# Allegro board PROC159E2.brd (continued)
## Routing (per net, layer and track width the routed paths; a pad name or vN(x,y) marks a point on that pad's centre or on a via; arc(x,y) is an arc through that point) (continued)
N34830437: length 5.6
  BOTTOM w0.147: C91.2 88.04,53.55 88.09,53.6 U13.8 ; C91.2 87.59,53.4 U13.9 ; C91.2 88.04,52.86 87.75,52.57 87.75,52.09 R70.1
N34869480: length 3.3
  TOP w0.147: R432.2 R431.2 82.51,35.37 82.19,35.05 U78.6
N34869775: length 1.3
  BOTTOM w0.147: C57.1 R29.2
N35052540: length 1.2
  BOTTOM w0.147: U17.5 103.31,13.13 R7.1
N35052638: length 1.7
  TOP w0.147: U4.10 95.02,15.27 94.85,15.1 R18.1
N35052879: length 2.3
  TOP w0.147: C9.1 99.43,18.92 99.8,18.55 U3.6
N35052899: length 2.1
  BOTTOM w0.147: R6.2 103.63,11.6 103.31,11.93 102.97,11.93 102.55,12.35 U17.6
N35052954: length 1.8
  BOTTOM w0.147: R2.2 103.54,15.18 103,14.63 103,14.22 102.7,13.93 U17.3
N35052969: length 2.8
  BOTTOM w0.147: U17.9 101.05,12.39 100.71,12.05 99.9,12.05 TP1.1
N35053013: length 1.9
  BOTTOM w0.147: R8.1 100,13.53 U17.11
N35053423: length 1.7
  TOP w0.147: C16.1 95.8,15.1 95.52,15.38 U4.11
N35053536: length 10.2
  BOTTOM w0.147: v1(78.3,21.45) 76.12,19.27 76.12,15.35 76.84,14.63 C24.1 R22.2
N35053695: length 2
  BOTTOM w0.147: U5.7 86.18,16.26 86.5,16.58 R23.1
N35053732: length 1.3
  BOTTOM w0.147: R24.1 C23.2
N35056553: length 1.7
  TOP w0.147: LD1.2 102.2,14.86 101.86,14.53 R1.2
N35059517: length 4.7
  TOP w0.147: U1.B10 v1(60.98,46.43)
  BOTTOM w0.147: R141.2 62.69,48.77 60.98,47.06 v1(60.98,46.43)
N35065419: length 12.4
  TOP w0.147: v1(103.42,36.08) 103.19,36.31 U7.12
  L08_SIG2 w0.091: v1(94.4,37.06) 94.77,37.06 95.22,36.61 100.67,36.61 101.82,35.46 102.79,35.46 v1(103.42,36.08)
  BOTTOM w0.147: R42.1 v1(94.4,37.06)
N35071225: length 10.1
  TOP w0.147: v1(106.62,35.3) 106.29,35.62 106.29,35.63 106.19,35.73 106.19,36.36 106.19,36.36 U7.18
  L03_SIG1 w0.091: v1(106.62,35.3) 107.21,34.7 107.21,29.91 v1(108.02,29.1)
  BOTTOM w0.147: v1(108.02,29.1) 107.57,28.65 R435.1
N35137924: length 4
  TOP w0.147: TP64.1 69.49,95.24 70.12,94.6 71.37,94.6 71.81,95.04 J8.38
N35139843: length 12.4
  TOP w0.147: U7.34 v1(104.69,46.09)
  L03_SIG1 w0.091: v1(111.04,53.24) 108.34,50.54 108.34,48.55 106.39,46.6 105.21,46.6 v1(104.69,46.09)
  BOTTOM w0.147: R142.1 110.92,53.12 v1(111.04,53.24)
N35230144: length 2.2
  TOP w0.147: U18.5 30.35,56.38 29.93,56.79 R439.1
N35230147: length 1.6
  TOP w0.147: U18.2 40.11,53.84 R440.1
N35230153: length 1.6
  TOP w0.147: U18.7 R442.1
N35244293: length 3.7
  TOP w0.147: R452.1 36.1,43.66 35.64,44.11 33.3,44.11 U19.D2
N35244332: length 3.2
  TOP w0.147: U19.C4 30.26,42.08 28.81,42.08 28.58,42.3 R453.1
N35244360: length 3.3
  TOP w0.147: R454.1 28.03,44.8 28.59,44.24 30.26,44.24 U19.D4
N35244387: length 2
  TOP w0.147: R455.1 28.48,43.57 28.71,43.8 29.25,43.8 29.39,43.66 U19.D5
N35244414: length 3.2
  TOP w0.147: R456.1 31.33,46.63 31.85,46.11 U19.E3
N35244441: length 3.4
  TOP w0.147: U19.E2 33.85,45.66 R457.1
N35244468: length 2.6
  TOP w0.147: U19.E1 34.38,44.66 35.13,45.41 R458.1
N35248046: length 4.3
  TOP w0.147: U19.D3 32.43,44.24 32.43,44.83 32.6,45.01 R451.1
N35252647: length 1.6
  TOP w0.147: U18.3 40.11,55.11 R441.1
N35271296: length 2
  TOP w0.147: TP78.1 17.96,25.36 18.42,24.91 U29.8
N35329968: length 5.4
  TOP w0.147: U1.L3 v1(54.58,38.43)
  BOTTOM w0.147: R117.2 51.52,39.69 52.77,38.43 v1(54.58,38.43)
N35329989: length 5.3
  TOP w0.147: U1.M3 v1(54.58,37.63)
  BOTTOM w0.147: R118.2 52.07,38.54 52.52,38.1 54.11,38.1 v1(54.58,37.63)
N35342843: length 1.5
  TOP w0.147: U57.15 44.2,105.26 R371.1
N35343433: length 1.6
  TOP w0.147: U57.14 44.07,103.99 R372.1
N35343436: length 1.5
  TOP w0.147: R373.1 44.2,102.72 U57.13
N35343439: length 1.6
  TOP w0.147: U57.12 44.07,101.45 R374.1
N35343442: length 1.5
  TOP w0.147: U57.11 44.2,100.18 R375.1
N35343445: length 1.5
  TOP w0.147: U57.10 44.2,98.91 R376.1
N35345342: length 1.8
  BOTTOM w0.147: R378.1 18.51,73.05 18.51,73.06 U58.7
N35373997: length 4.6
  TOP w0.147: v1(43.94,78.73) U46.5 41.91,78.73 41.28,79.36 R315.1
  BOTTOM w0.147: v1(43.94,78.73) 44.18,78.48 R314.1
N35375175: length 2.1
  BOTTOM w0.147: R34.1 J20.1
N35376496: length 3.2
  BOTTOM w0.147: R31.1 R175.2 17.69,17.25 17.71,17.22 J21.1
N35387120: length 3.5
  TOP w0.147: U29.7 22.59,24.91 22.9,25.22 22.9,26.45 23.28,26.83 R116.1
N35387809: length 4.6
  TOP w0.147: v1(44.79,41.82) 43.93,40.95 R1678.1
  BOTTOM w0.147: v1(44.79,41.82) 43.79,40.82 U80.8
N35395797: length 2.2
  TOP w0.147: U20.15 52.77,64.96 53.35,64.38 R461.1
N35537520: length 11.8
  TOP w0.147: v1(90.8,35.17) 91.18,34.79 94.86,34.79 95.27,34.38 R20.1 95.28,32.65 95.69,32.24 95.69,32.22 95.72,32.19 Q13.4
  BOTTOM w0.147: R469.1 89.85,34.21 v1(90.8,35.17)
N35538921: length 2.2
  BOTTOM w0.147: Q12.3 88.42,33.07 88.87,32.62 R469.2
N35654609: length 1.7
  TOP w0.147: Q20.2 R3832.2
N35654631: length 1.7
  TOP w0.147: LD19.2 Q20.3
N35656175: length 1.3
  TOP w0.147: LD2.2 R47.2
N35656498: length 1.3
  TOP w0.381: R3833.2 LD20.2
N35656998: length 1.1
  TOP w0.147: R3834.2 LD21.2
N35657235: length 1.3
  TOP w0.381: R3835.2 LD22.2
N35672996: length 3.3
  TOP w0.147: SW15.2 62.89,55.21 62.51,55.59 R3842.2
N35712813: length 56.6
  TOP w0.147: J22.2 72.06,23.08 67.23,23.08 65.88,21.73 50.86,21.73 47.58,25.01 40.89,25.01 40.05,25.84 39.14,25.84 37.94,27.04 37.94,28.66 36.88,29.73 27.1,29.73 24.79,27.42 R116.2
N35805242: length 14.2
  TOP w0.147: v1(76.94,48.25) 76.94,46.83 75.55,45.44 70.26,45.44 67.99,43.17 67.32,43.17 U1.F18
  BOTTOM w0.147: R247.1 77.2,48.5 v1(76.94,48.25)
N35805430: length 8.2
  TOP w0.147: U1.C18 67.69,45.23 69.37,46.91 71.11,46.91 v1(72.71,48.51)
  BOTTOM w0.147: v1(72.71,48.51) 73.07,48.51 73.21,48.66 R255.1
N35805533: length 16.9
  TOP w0.147: v1(75.59,46.26) 76.34,47.01 76.34,48.81 76.82,49.29 R248.1 ; U1.G16 v1(65.78,42.43)
  BOTTOM w0.114: v1(65.78,42.43) 65.78,42.43 66.18,42.03 67.63,42.03 67.8,42.2
  BOTTOM w0.147: 67.8,42.2 68.66,43.06 68.66,44.82 69.92,46.08 74.96,46.08 75.14,46.26 v1(75.59,46.26)
N35805539: length 12.7
  TOP w0.147: U1.E17 66.58,44.03 67.97,44.03 69.97,46.03 73.99,46.03 74.75,46.79 74.75,47.85 75.64,48.73 R249.1
N35805550: length 12.3
  TOP w0.147: U1.E18 68.04,43.63 70.14,45.73 74.17,45.73 75.56,47.12 v1(75.56,47.99)
  BOTTOM w0.147: R250.1 75.73,48.61 75.56,48.44 v1(75.56,47.99)
N35805561: length 13.7
  TOP w0.147: R251.1 74.42,48.31 73.93,47.82 v1(73.93,46.78) ; U1.F16 v1(65.78,43.23)
  BOTTOM w0.114: v1(65.78,43.23) 65.78,43.23 66.18,42.83 66.88,42.83 67.07,43.02
  BOTTOM w0.147: v1(73.93,46.78) 73.34,46.78 73.05,46.49 69.73,46.49 67.95,44.71 67.95,43.9 67.07,43.02
N35805574: length 10.2
  TOP w0.147: U1.F15 v1(64.98,43.23)
  BOTTOM w0.114: 66.36,43.84 66.15,43.63 65.38,43.63 v1(64.98,43.23)
  BOTTOM w0.147: R252.1 70.85,47.2 70.49,46.84 69.36,46.84 66.36,43.84
N35805586: length 9.5
  TOP w0.147: R253.1 71.98,48.31 71.03,47.37 v1(70.27,47.37) ; U1.E16 v1(65.78,44.03)
  BOTTOM w0.147: v1(65.78,44.03) 69.12,47.37 v1(70.27,47.37)
N35805597: length 9.8
  TOP w0.147: U1.D18 67.82,44.43 69.71,46.32 71.74,46.32 v1(73.93,48.51)
  BOTTOM w0.147: R254.1 74.43,48.66 74.29,48.51 v1(73.93,48.51)
N35805610: length 9.6
  TOP w0.147: R256.1 73.2,48.31 71.5,46.62 69.59,46.62 67.79,44.82 66.57,44.82 U1.D17
N35805636: length 5.7
  TOP w0.147: v1(70.27,48.51) 69.81,48.51 69.57,48.27 69.57,48.14 67.46,46.03 U1.B18
  BOTTOM w0.147: R257.1 69.63,48.68 69.8,48.51 v1(70.27,48.51)
N35805639: length 5.1
  TOP w0.147: R258.1 69.54,48.68 67.28,46.42 66.57,46.42 U1.B17
N35805644: length 6.1
  TOP w0.147: U1.D16 v1(65.78,44.83)
  BOTTOM w0.147: R259.1 68.41,47.46 v1(65.78,44.83)
N35805649: length 6.9
  TOP w0.147: U1.C17 66.57,45.62 67.53,45.62 69.8,47.89 70.41,47.89 70.76,48.24 R260.1
N35805656: length 3.8
  TOP w0.147: U1.A17 66.52,47.17 66.52,48.24 67.57,49.29 R261.1
N35805662: length 4.8
  TOP w0.147: U1.C16 v1(65.78,45.63)
  BOTTOM w0.147: v1(65.78,45.63) 66.35,46.2 66.35,47.12 67.19,47.96 R262.1
N35805667: length 5.5
  TOP w0.147: U1.C15 v1(64.98,45.63) ; v1(66.22,48.87) 66.43,49.08 R1652.1
  BOTTOM w0.114: 65.38,47.56 65.38,46.03 v1(64.98,45.63)
  BOTTOM w0.147: v1(66.22,48.87) 65.38,48.03 65.38,47.56
N35805672: length 6.1
  TOP w0.147: U1.D15 v1(64.98,44.83) ; R1653.1 v1(65.2,48.85)
  BOTTOM w0.114: 64.58,47.56 64.58,45.23 v1(64.98,44.83)
  BOTTOM w0.147: 64.58,47.56 64.58,48.24 v1(65.2,48.85)
N35820709: length 1.6
  TOP w0.147: SW14.2 R3858.2
N35821153: length 4.8
  BOTTOM w0.147: U88.19 83.59,107.33 83.93,107.67 86.37,107.67 86.59,107.46 R1399.2
N35824901: length 1.9
  BOTTOM w0.147: U81.9 70.82,29.38 70.37,29.83 R475.2
N35842882: length 1.6
  BOTTOM w0.147: R3870.2 U90.9
N35844058: length 1.6
  TOP w0.147: SW16.2 R3872.2

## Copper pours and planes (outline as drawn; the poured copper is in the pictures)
DGND on TOP (solid shape): 92.69,98 90.51,98 90.51,105.68 92.69,105.68
DGND on TOP (solid shape): 71.89,87.53 72.1,87.53 72.1,86.46 69.99,86.46 69.27,87.18 69.27,87.62 71.4,87.62 71.53,87.74 71.89,87.74
DGND on TOP (solid shape): 47.7,66.96 47.47,66.96 47.47,67.16 46.43,67.16 46.43,66.96 46.23,66.96 45.59,66.33 45.59,65.99 44.83,65.99 44.83,66.92 45.78,67.87 47.7,67.87
DGND on TOP (solid shape): 43.08,60.62 43.19,60.65 43.25,60.55 43.25,60.16 44.49,58.92 44.49,58.47 44.43,58.38 44.32,58.4 42.77,59.95 42.77,60.31
DGND on TOP (solid shape): 42.2,62.25 42.23,62.3 42.29,62.29 42.67,61.9 42.67,61 42.38,60.7 42.26,60.68 42.2,60.77 42.2,60.87 41.22,60.87 41.22,62.01 41.02,62.01 41.02,62.24 42.2,62.24
DGND on TOP (solid shape): 48.14,33.61 48.33,33.61 48.33,33.41 49.46,33.41 49.46,32.43 51.4,32.43 51.4,32.67 51.65,32.67 51.87,32.89 51.98,32.91 52.04,32.82 52.04,32.36 51.58,31.9 51.3,31.9 51.3,32.08 49.55,32.08 49.55,31.1 49.37,31.1 49.37,31.3 48.33,31.3 48.33,31.1 47.84,31.1 47.84,32.58 46.64,32.58 46.64,34.13 47.62,34.13
DGND on TOP (solid shape): 58.23,77.22 58.25,77.11 58.16,77.05 58.01,77.05 56.59,75.62 56.47,75.6 56.41,75.7 56.41,77.72 55.73,78.4 55.71,78.51 55.8,78.57 56.88,78.57
DGND on TOP (solid shape): 87.32,19.34 87.44,19.36 87.5,19.27 87.5,15.93 88.26,15.17 88.29,15.06 88.19,14.99 83.58,14.99 83.49,15.04 83.48,15.13 83.5,15.21 83.49,15.3 83.52,15.38 83.59,15.41 86.48,15.41 86.48,18.5
DGND on TOP (solid shape): 105.1,89.79 105.07,89.7 105.06,89.61 105.06,88.66 104.49,88.66 104.32,88.63 104.17,88.54 104.15,88.53 104.12,88.53 104.12,88.5 104.11,88.49 103.99,88.26 104,88.01 103.99,87.92 103.91,87.88 102.93,87.88 102.83,87.94 102.85,88.05 104.75,89.94 105.1,89.94
DGND on TOP (solid shape): 43.19,27.3 43.26,27.4 43.37,27.37 43.49,27.27 43.64,27.23 43.66,27.23 44.99,25.89 45.01,25.78 44.92,25.72 41.23,25.72 40.42,26.53 39.44,26.53 39.37,26.6 39.35,26.71 39.44,26.77 40.16,26.77 40.16,27.32 40.75,27.32 40.75,27.29 41.79,27.29 41.79,27.32 42.15,27.32 42.15,27.29 43.19,27.29
DGND on TOP (solid shape): 51.75,36.56 51.84,36.53 52.22,36.15 52.96,36.15 53,36.1 53.02,36.03 53,35.96 52.96,35.91 52.54,35.91 51.67,35.04 51.56,35.01 51.5,35.11 51.5,35.15 50.64,35.15 50.64,35.59 51.05,35.59 51.12,35.6 51.19,35.62 51.43,35.62 51.43,35.88 51.44,35.94 51.45,35.98 51.45,36.24 51.6,36.39 51.64,36.45 51.68,36.5
DGND on TOP (solid shape): 81.82,88.89 81.92,88.87 82.81,87.97 84.71,87.97 85.49,87.19 85.49,85.96 85.43,85.87 85.32,85.89 85.01,86.19 82.35,86.19 81.68,86.86 81.68,86.88 81.62,87.05 81.49,87.18 81.44,87.25 81.47,87.34 81.52,87.39 81.52,88.45 81.46,88.51 81.5,88.55 81.51,88.56 81.66,88.67 81.75,88.83
DGND on TOP (solid shape): 69.37,94.92 69.44,94.89 69.56,94.78 69.59,94.69 69.54,94.62 69.42,94.48 69.38,94.3 69.38,94.13 69.34,94.13 69.34,93.29 70,93.29 70,92.15 70.96,92.15 70.96,92.22 71.22,92.22 71.32,92.31 71.61,92.31 71.73,92.19 71.89,92.19 71.89,91.72 71.67,91.72 71.52,91.57 71.5,91.57 71.38,91.54 71.27,91.47 70.91,91.83 69.36,91.83 69,92.2 69,94.5 68.99,94.52 68.96,94.61 69.02,94.69 69.17,94.76 69.29,94.88
DGND on TOP (solid shape): 85.07,85.35 85.07,84.75 85.91,83.91 85.91,82.62 85.85,82.53 85.74,82.55 85.16,83.12 84.16,83.12 83.56,82.53 83.29,82.53 83.2,82.55 83.11,82.56 82.53,82.56 82.38,82.53 82.24,82.46 82.13,82.44 82.07,82.54 82.07,83.31 82.14,83.4 82.25,83.38 82.52,83.28 82.79,83.39 83.25,83.85 83.25,83.95 83.34,83.95 83.34,84.99 82.38,84.99 82.38,84.09 82.24,83.95 82.2,83.91 82.17,83.86 82.07,83.88 82.07,85.64 84.78,85.64
DGND on TOP (solid shape): 98.94,90.34 99,90.44 99.11,90.42 99.14,90.39 99.14,88.98 98.62,88.46 98.62,87.22 97.19,85.79 97.08,85.77 97.02,85.86 97.02,86.93 97.08,87.02 97.19,87 98.22,87.1 98.05,88.13 98.05,88.28 98.46,88.69 98.57,88.96 98.45,89.3 98.48,89.37 98.94,89.83
DGND on TOP (solid shape): 37.67,28.55 37.67,27.39 36.78,27.39 36.7,27.43 36.69,27.53 36.46,28.03 35.97,27.78 35.9,27.71 35.8,27.73 35.45,28.08 34.37,28.08 34.37,28.69 32.95,28.69 32.95,27.98 27.73,27.98 27.63,28.04 27.65,28.15 28.43,28.92 29.96,28.92 30.43,28.88 30.58,29.32 30.6,29.41 30.68,29.45 36.76,29.45
DGND on TOP (solid shape): 82.66,92.94 82.72,93.03 82.83,93.01 82.85,92.99 84.79,92.99 84.79,90.57 85.1,90.27 85.25,90.17 85.42,90.13 85.67,90.13 85.84,90.17 85.99,90.27 86.22,90.5 86.29,90.48 86.34,90.47 86.38,90.46 86.38,90.23 86.34,90.23 86.04,90.01 86.05,89.65 86.06,89.54 85.97,89.49 85.02,89.49 85.02,88.53 84.96,88.51 84.94,88.52 83.04,88.52 81.71,89.86 81.71,89.88 81.59,90.12 81.35,90.23 81.31,90.24 81.3,90.28 81.3,92.45 81.62,92.45 81.62,92.36 82.66,92.36
DGND on TOP (solid shape): 82.34,69.56 82.4,69.47 82.4,69.32 82.49,69.32 82.49,68.89 82.93,68.45 82.93,67.38 82.89,67.3 82.8,67.28 82.31,66.92 82.8,66.55 82.89,66.53 82.93,66.45 82.93,65.07 82.9,65.01 82.89,64.97 82.82,64.9 82.72,64.93 81.76,65.88 81.76,69.31 81.8,69.39 81.88,69.41 82.07,69.43 82.23,69.53
DGND on TOP (solid shape): 98.87,85.47 98.92,85.45 98.91,85.39 98.84,85.21 98.86,85.02 98.85,84.92 98.77,84.87 98.69,84.87 98.69,82.93 98.82,82.93 98.82,82.59 96.37,80.14 95.53,80.14 95.24,80.02 95.14,79.71 95.14,79.69 95.09,79.64 95.04,79.69 95.04,81.13 97.56,83.65 97.67,83.67 97.73,83.57 97.73,82.93 96.11,81.31 96.09,81.3 95.94,80.67 96.57,80.83 96.57,80.84 98.39,82.65 98.39,85.1 98.76,85.47
DGND on TOP (solid shape): 30.79,8.02 30.9,8.04 30.96,7.95 30.96,6.36 30.92,6.28 30.84,6.26 30.4,5.88 30.84,5.5 30.92,5.48 30.96,5.4 30.96,4.59 31.11,4.44 31.14,4.41 31.14,4.4 31.46,4.09 31.47,4.03 31.42,4 31.36,4 31.36,2.35 30.72,2.35 30.72,4 30.69,4 30.69,4.26 30.24,4.72 30.24,6.21 30.28,6.21 30.62,6.59 30.28,6.97 30.24,6.97 30.24,7.47
DGND on TOP (solid shape): 73.96,89.53 74.2,89.41 74.46,89.44 74.56,89.43 74.6,89.35 74.6,88.73 74.81,88.73 74.86,88.68 74.88,88.64 74.86,88.6 74.81,88.56 74.6,88.56 74.6,87.93 74.81,87.93 74.96,87.82 75.14,87.79 75.26,87.79 75.26,87.58 74.8,87.58 74.8,87.49 75,87.49 75,87.13 74.8,87.13 74.8,86.86 72.77,86.86 72.77,87.13 72.57,87.13 72.57,87.49 72.77,87.49 72.77,87.53 72.96,87.53 72.96,87.57 73.11,87.57 73.28,87.74 73.3,87.75 73.65,88.15 73.25,88.51 73.18,88.53 73.15,88.61 73.15,89.14 72.96,89.14 72.96,89.79 73.22,89.79 73.28,89.84 73.65,89.84
DGND on TOP (solid shape): outline of 128 points within 62.52,61.98 70.88,67
DGND on TOP (solid shape): 88.9,12.75 88.93,12.8 88.99,12.79 89.05,12.73 89.05,12.09 89.83,11.3 92.18,11.3 94.8,8.68 95.34,8.68 95.44,8.61 95.42,8.5 94.57,7.66 94.57,4.04 94.75,3.86 94.75,2.65 94.12,2.65 94.12,4 94.09,4 94.09,7.68 93.46,8.31 93.43,8.42 93.52,8.48 93.73,9.17 93.14,8.77 93.12,8.68 93.04,8.64 93,8.64 92.92,8.68 92.9,8.77 92.87,9.06 92.66,9.28 92.6,9.36 92.65,9.45 92.49,10.16 92.2,9.5 92.23,9.39 92.13,9.32 89.81,9.32 89.08,8.59 88.97,8.57 88.9,8.66
DGND on TOP (solid shape): 77.69,103.59 77.8,103.61 77.86,103.52 77.86,100.67 77.81,100.58 77.71,100.58 77.14,100.25 77.71,99.92 77.81,99.92 77.86,99.83 77.86,96.49 77.87,96.49 77.9,96.4 77.84,96.32 77.74,96.25 77.66,96.14 77.63,96.12 77.6,96.11 77.53,96.13 77.45,96.14 77.35,96.14 77.34,96.18 77.28,96.36 77.15,96.5 77.11,96.59 77.15,96.67 77.32,97.18 76.89,97.5 76.05,97.5 75.84,97.29 75.74,97.27 75.67,97.36 75.47,97.36 75.47,98.61 72.1,98.61 72.1,97.65 69.08,97.65 69.08,95.91 69.04,95.83 68.96,95.81 68.77,95.82 68.59,95.77 68.49,95.77 68.44,95.86 68.44,98.37 68.95,98.88 75.61,98.88 76.85,100.12 76.95,100.62 76.43,100.96 76.45,101.07 76.83,101.44 76.83,102.73
DGND on TOP (solid shape): outline of 198 points within 46.15,60.55 52.61,66.79
DGND on TOP (solid shape): outline of 247 points within 64,2.55 67.44,12.89
DGND on TOP (solid shape): outline of 273 points within 83.99,64.39 88.44,80.81
DGND on TOP (solid shape): outline of 116 points within 71.49,90.33 75.52,98.03
DGND on TOP (solid shape): outline of 321 points within 58.65,91.03 67.26,99.36
DGND on TOP (solid shape): outline of 323 points within 80.74,42.73 93.98,56.92
DGND on TOP (solid shape): outline of 149 points within 27.18,57.03 44.2,68.43
DGND on TOP (solid shape): outline of 139 points within 81.3,95.64 88.4,105.86
DGND on TOP (solid shape): outline of 545 points within 98.63,2.65 108.73,9.48
DGND on TOP (solid shape): outline of 549 points within 62.13,14.63 82.76,22.8
DGND on TOP (solid shape): outline of 730 points within 67.34,34.33 83.76,51
DGND on TOP (solid shape): outline of 959 points within 43.1,22.6 68.58,31.35
DGND on TOP (solid shape): outline of 1416 points within 35.77,28.23 50.66,50.34
DGND on TOP (solid shape): outline of 1476 points within 53,26.7 82.83,36.96
DGND on TOP (solid shape): outline of 1628 points within 41.27,85.44 75.61,108.19
DGND on TOP (solid shape): outline of 2125 points within 31.51,2.35 63.43,21.45
DGND on TOP (solid shape): outline of 2328 points within 44.35,43.18 69.78,66.79
DGND on TOP (solid shape): outline of 2452 points within 86.77,55.25 113.74,108.19
DGND on TOP (solid shape): outline of 2377 points within 22.19,32.65 44.34,62.34
DGND on TOP (solid shape): outline of 2783 points within 46.03,63.51 75.56,94.26
DGND on TOP (solid shape): outline of 2885 points within 72.58,2.65 113.74,59.55
DGND on TOP (solid shape): outline of 5063 points within 10.02,2.35 50.67,78.39
DGND on L03_SIG1 (solid shape): 77.5,56.44 75.63,54.57 75.52,54.55 75.46,54.64 75.46,59.37 75.59,59.51 77.5,59.51
DGND on L03_SIG1 (solid shape): 93.22,103.64 93.22,103.6 93.16,103.5 93.05,103.53 92.7,103.87 90.49,103.87 90.39,103.97 90.39,104.32 92.55,104.32
DGND on L03_SIG1 (solid shape): 93.28,86.42 93.28,84.03 93.33,83.98 93.28,83.93 93.26,83.93 93.17,83.95 93.13,84.03 93.13,85.62 92.64,86.11 90.77,86.11 90.51,86.37 90.51,86.96 92.73,86.96
DGND on L03_SIG1 (solid shape): 70.5,99.43 71.75,98.19 71.75,97.12 71.69,97.03 71.58,97.05 70.73,97.9 70.73,99 70.34,99.39 70.4,99.44
DGND on L03_SIG1 (solid shape): 34.89,55.39 34.91,55.27 34.82,55.21 33.98,55.21 30.65,58.54 30.63,58.65 30.72,58.71 31.56,58.71
DGND on L03_SIG1 (solid shape): 72.83,39.93 72.92,39.87 72.9,39.76 72.54,39.41 69.94,39.41 69.85,39.47 69.87,39.58 70.22,39.93
DGND on L03_SIG1 (solid shape): 77.52,62.87 77.62,62.8 77.6,62.69 77.26,62.36 75.3,62.36 74.95,62 74.89,61.99 74.86,62.04 74.86,62.17 75.55,62.87
DGND on L03_SIG1 (solid shape): 88.02,70.38 88.13,70.4 88.19,70.31 88.19,66.95 87.88,66.64 87.77,66.62 87.71,66.71 87.71,70.07
DGND on L03_SIG1 (solid shape): 89.19,70.66 89.3,70.69 89.37,70.59 89.37,67.03 89.14,66.81 89.03,66.79 88.97,66.88 88.97,70.44
DGND on L03_SIG1 (solid shape): 91.39,56.24 91.46,56.33 91.57,56.31 92.29,55.59 92.29,53.62 92.22,53.52 92.11,53.55 91.39,54.27
DGND on L03_SIG1 (solid shape): 93.05,82.95 93.16,82.97 93.22,82.88 93.22,78.14 92.83,77.75 92.72,77.73 92.66,77.82 92.66,82.56
DGND on L03_SIG1 (solid shape): 95.58,70.9 95.64,70.99 95.75,70.97 96.18,70.54 96.18,66.27 96.12,66.18 96.01,66.2 95.58,66.63
DGND on L03_SIG1 (solid shape): 59.75,31.7 59.86,31.72 59.92,31.63 59.92,31.43 59.57,31.07 59.57,29.34 58.68,28.45 58.1,28.45 57.83,28.17 57.77,28.22 57.78,28.28 57.78,28.34 58.62,29.18 58.62,30.57
DGND on L03_SIG1 (solid shape): 77.49,61.89 77.55,61.9 77.58,61.85 77.58,60.3 77.29,60.01 75.39,60.01 75.36,59.98 75.25,59.96 75.18,60.05 75.18,61.53 75.51,61.86 77.47,61.86
DGND on L03_SIG1 (solid shape): 87.06,48.83 87.13,48.92 87.24,48.9 87.6,48.54 87.6,47.15 86.92,46.48 86.81,46.46 86.75,46.55 86.75,46.94 87.06,47.25
DGND on L03_SIG1 (solid shape): 87.61,80.14 87.72,80.16 87.78,80.06 87.78,77.5 88.84,76.44 88.84,76.07 88.78,75.98 88.67,76 87.58,77.09 87.58,80.11
DGND on L03_SIG1 (solid shape): 89.41,45.14 89.5,45.08 89.48,44.96 89.42,44.91 89.42,41.46 88.3,40.33 88.19,40.31 88.12,40.4 88.12,44.24 89.02,45.14
DGND on L03_SIG1 (solid shape): 104.47,44.39 104.57,44.32 104.54,44.21 103.64,43.31 103.64,38.91 101.48,36.74 101.42,36.73 101.39,36.78 101.39,36.82 103.18,38.61 103.18,43.16 104.41,44.39
DGND on L03_SIG1 (solid shape): 70.24,45.31 70.35,45.33 70.41,45.23 70.41,45.2 70.77,44.84 70.39,44.46 69.66,44.46 67.81,42.61 67.73,42.58 67.65,42.62 67.63,42.65 67.63,42.7
DGND on L03_SIG1 (solid shape): 71.91,68.34 72.02,68.36 72.08,68.27 72.08,68.24 72.54,67.78 71.7,66.94 71.46,67.18 71.42,67.18 71.32,67.24 71.34,67.35 71.4,67.41 71.4,67.83
DGND on L03_SIG1 (solid shape): 89.38,48.84 89.44,48.93 89.55,48.91 89.78,48.68 89.78,46.24 89.45,45.91 88.7,45.91 87.75,44.96 87.64,44.94 87.57,45.03 87.57,45.55 89.38,47.36
DGND on L03_SIG1 (solid shape): 94.62,60.88 94.73,60.9 94.79,60.81 94.79,60.33 95.51,59.6 95.51,50.72 94.9,50.11 94.79,50.08 94.72,50.18 94.72,57.06 93.81,57.98 93.81,60.07
DGND on L03_SIG1 (solid shape): 55.72,29.71 55.84,29.74 55.9,29.64 55.9,29.47 55.9,20.85 55.84,20.76 55.73,20.78 55.54,20.96 55.54,29.53
DGND on L03_SIG1 (solid shape): 79.71,29.3 79.77,29.39 79.88,29.37 81.17,28.08 81.17,26.83 81.11,26.74 81,26.76 80.88,26.87 80.54,26.87 80.54,27.45 80.07,27.92 80.07,28.71 79.71,29.08
DGND on L03_SIG1 (solid shape): 88.76,57.32 88.82,57.42 88.93,57.39 88.97,57.36 88.97,53.15 89.42,52.7 89.42,51.4 90.6,50.21 90.6,49.58 90.54,49.49 90.43,49.51 88.71,51.23 88.71,56.84 88.51,57.03 88.76,57.28
DGND on L03_SIG1 (solid shape): 19.08,14.59 19.19,14.61 19.25,14.52 19.25,10.18 19.48,9.95 19.48,7.95 19.41,7.86 19.3,7.88 19.18,7.96 19.03,7.99 19.01,7.99 18.62,8.38 18.62,14.13
DGND on L03_SIG1 (solid shape): 93.39,45.44 92.72,44.78 92.72,41.79 91.74,40.81 91.63,40.79 91.57,40.88 91.57,43.94 93.21,45.58 93.21,47.82 92.78,48.24 92.78,48.45 92.91,48.45 93.01,48.47 93.09,48.53 93.22,48.66 93.26,48.71 93.29,48.77 93.3,48.81 93.39,48.81
DGND on L03_SIG1 (solid shape): 108.21,45.71 108.31,45.65 108.29,45.53 106.74,43.99 106.74,38.93 106.3,38.49 104.41,38.49 103.51,37.59 103.27,37.59 103.18,37.65 103.2,37.76 104.14,38.7 104.14,43.1 105.04,44.01 106.46,44.01 108.16,45.71
DGND on L03_SIG1 (solid shape): 60.84,39.6 60.9,39.69 61.02,39.67 61.25,39.44 62.66,39.44 62.72,39.38 62.72,37.32 63.08,36.96 63.07,36.93 63.05,36.87 63.05,36.8 63.03,36.72 62.95,36.69 62.46,36.69 62.42,36.73 62.42,37.16 62.09,37.49 60.91,37.49 60.84,37.56
DGND on L03_SIG1 (solid shape): 68.38,64.77 68.49,64.8 68.55,64.7 68.55,64.62 69.04,64.13 69.59,64.13 69.66,64.2 69.71,64.21 69.74,64.16 69.74,56.27 69.71,56.22 69.66,56.23 69.61,56.28 68.14,56.28 67.7,56.72 67.7,64.1
DGND on L03_SIG1 (solid shape): 90.72,59.32 90.83,59.34 90.9,59.25 90.9,54.06 91.52,53.44 91.54,53.36 91.49,53.28 91.4,53.2 91.34,53.09 91.26,53.03 91.17,53.06 90.43,53.79 90.43,59.03
DGND on L03_SIG1 (solid shape): 83.81,68.72 83.9,68.75 83.97,68.69 84.01,68.63 84.05,68.57 84.09,68.5 84.06,68.43 83.85,68.22 83.85,67.72 82.29,67.72 81.91,67.34 81.1,67.34 80.25,68.19 80.25,68.22 80.28,68.27 80.33,68.25 80.5,68.08 83.17,68.08
DGND on L03_SIG1 (solid shape): 23.93,15.87 24.04,15.85 24.07,15.81 24.07,9.44 22.71,8.08 22.71,6.91 22.64,6.81 22.53,6.84 22.49,6.88 22.49,8.65 23.65,9.81 23.65,15.3 23.74,15.39 23.74,15.57 23.82,15.67 23.86,15.79
DGND on L03_SIG1 (solid shape): 90.97,87.98 92.43,87.98 92.78,87.63 92.8,87.52 92.71,87.46 90.59,87.46 89.51,88.54 89.5,88.54 89.41,88.58 89.41,88.68 89.44,88.8 89.43,88.93 89.45,89.02 89.53,89.06 89.9,89.06
DGND on L03_SIG1 (solid shape): 38.62,53.09 38.71,53.03 38.69,52.92 37.49,51.71 36.56,51.71 36.48,51.75 36.46,51.83 36.46,51.86 36.46,51.98 36.44,52.08 36.38,52.16 36.22,52.32 31.86,52.32 30.69,51.15 30.64,51.15 30.6,51.18 30.61,51.23 32.47,53.09
DGND on L03_SIG1 (solid shape): 46.32,36.53 46.32,35.82 46.49,35.65 46.33,35.5 45.53,35.5 45.46,35.53 45.43,35.62 45.35,35.93 45.05,36.06 45.03,36.06 44.78,36.3 44.76,36.39 44.82,36.47 44.89,36.51 44.96,36.57 46.28,36.57
DGND on L03_SIG1 (solid shape): 48.24,93.31 48.36,93.33 48.42,93.24 48.42,92.03 51.01,89.44 51.04,89.36 50.99,89.28 50.84,89.14 50.8,88.94 50.8,88.92 47.92,86.04 47.8,86.02 47.74,86.11 47.74,92.81
DGND on L03_SIG1 (solid shape): 90.14,85.79 90.21,85.88 90.32,85.86 90.57,85.61 92.43,85.61 92.63,85.42 92.63,84.01 92.59,83.92 92.49,83.91 92.36,83.94 92.23,83.92 92.14,83.93 92.1,84.02 92.1,84.16 91.48,84.77 90.92,84.77 90.14,85.55
DGND on L03_SIG1 (solid shape): 95.71,82.72 95.75,82.71 95.81,82.69 95.87,82.69 96.09,82.69 96.09,81.83 94.79,80.53 94.68,80.51 94.61,80.6 94.61,82.44 94.86,82.69 94.94,82.71 95.02,82.67 95.36,82.48 95.68,82.69
DGND on L03_SIG1 (solid shape): 85.65,93.9 85.73,93.85 85.83,93.83 86.07,93.83 86.16,93.76 86.14,93.65 84.88,92.39 84.88,85.16 84.82,85.07 84.71,85.09 84.56,85.23 82.86,85.23 82.71,85.39 82.71,92.77 83.77,93.83 84.62,93.83 84.81,94.01 84.92,93.9 85,93.85 85.1,93.83 85.25,93.83 85.34,93.85 85.42,93.9 85.54,94.01
DGND on L03_SIG1 (solid shape): 32.34,14.44 32.44,14.47 32.51,14.39 32.66,14.14 32.95,14.07 33.03,14.05 33.07,13.97 33.07,7.28 32.33,6.55 32.25,6.52 32.18,6.56 32.04,6.68 31.87,6.72 31.84,6.72 31.57,6.99 31.57,9.73 32.13,10.3 32.13,14.24
DGND on L03_SIG1 (solid shape): 56.32,44.09 56.32,42.86 56.29,42.79 56.21,42.76 56.17,42.76 56.13,42.76 56.05,42.78 56.02,42.86 56.02,42.95 55.71,43.25 55.71,43.27 55.61,43.47 55.41,43.56 55.4,43.56 55.35,43.61 55.44,43.71 55.46,43.71 55.65,43.84 55.71,44.06 55.74,44.14 55.81,44.17 56.24,44.17
DGND on L03_SIG1 (solid shape): 53.12,47.29 53.12,47.07 52.61,47.07 50.46,44.92 50.35,44.9 50.28,44.99 50.28,45.69 50.66,46.06 50.74,46.09 50.81,46.05 51.39,46 51.34,46.58 51.3,46.66 51.33,46.74 51.96,47.37 53.04,47.37
DGND on L03_SIG1 (solid shape): 82.78,44.8 82.85,44.9 82.96,44.86 83.81,44.42 84.65,44.86 84.77,44.9 84.84,44.8 84.84,43.5 83.28,41.94 83.28,36.4 83.24,36.36 83.19,36.37 83.15,36.4 83.07,36.46 82.98,36.48 82.78,36.48
DGND on L03_SIG1 (solid shape): 92.23,105.68 92.31,105.62 92.4,105.6 92.64,105.6 92.73,105.54 92.71,105.43 92.67,105.39 92.67,105.21 92.55,105.09 90.75,105.09 90.32,105.52 90.31,105.57 90.45,105.62 90.54,105.68 90.65,105.79 90.76,105.68 90.84,105.62 90.94,105.6 91.09,105.6 91.19,105.62 91.27,105.68 91.38,105.79 91.5,105.68 91.58,105.62 91.67,105.6 91.82,105.6 91.92,105.62 92,105.68 92.11,105.79
DGND on L03_SIG1 (solid shape): 80.84,44.03 80.84,43.28 80.8,43.2 80.72,43.18 80.26,42.92 80.5,42.45 80.57,42.38 80.54,42.29 79.48,41.22 79.42,41.28 79.43,41.36 79.43,41.51 79.42,41.6 79.36,41.69 79.25,41.79 79.17,41.85 79.08,41.87 78.85,41.87 78.85,42.31 80.65,44.11 80.65,44.13 80.71,44.16
DGND on L03_SIG1 (solid shape): 65.78,29.13 65.88,29.16 65.95,29.07 66.12,28.79 66.44,28.75 66.54,28.73 66.58,28.65 66.58,26.63 66.21,26.26 66.09,26.24 66.03,26.34 65.91,26.64 65.59,26.73 65.5,26.75 65.47,26.83 65.47,28.82
DGND on L03_SIG1 (solid shape): 80.74,40.73 80.85,40.76 80.91,40.66 80.91,40.65 80.93,40.55 80.98,40.47 81.19,40.26 81.92,40.26 81.92,39.65 81.56,39.29 81.48,39.26 81.41,39.3 81.38,39.33 81.18,39.54 81.1,39.54 81.1,39.6 81.1,39.62 80.76,40.17 80.43,39.62 80.43,39.6 80.43,39.54 80.26,39.54 80.26,40.25
DGND on L03_SIG1 (solid shape): 90.56,71.87 90.67,71.89 90.73,71.8 90.73,71.35 91.35,70.74 91.35,65.82 92.16,65 92.16,64.6 92.12,64.52 92.03,64.51 91.54,64.14 92.03,63.78 92.12,63.76 92.16,63.68 92.16,62.55 92.1,62.46 91.99,62.48 91.68,62.79 89.81,62.79 89.55,63.05 89.55,65.89 90.2,66.55 90.2,71.52
DGND on L03_SIG1 (solid shape): 45.78,41.4 45.82,41.42 45.85,41.4 45.93,41.35 46.02,41.34 46.29,41.34 46.31,41.31 46.33,41.28 46.41,41.2 46.49,41.15 46.59,41.13 46.65,41.13 46.65,41.07 46.67,40.97 46.72,40.89 46.8,40.81 46.88,40.76 46.98,40.74 47.04,40.74 47.04,40.64 47.02,40.55 46.94,40.52 46.72,40.52 46.56,40.36 46.49,40.33 46.33,40.44 46.25,40.49 46.15,40.51 46.1,40.51 46.1,40.57 46.08,40.67 46.02,40.75 45.94,40.83 45.86,40.88 45.77,40.9 45.71,40.9 45.71,40.99 45.69,41.09 45.64,41.17 45.59,41.21
DGND on L03_SIG1 (solid shape): 34.31,61.27 34.41,61.21 34.38,61.1 33.8,60.51 33.7,60.49 33.63,60.55 32.89,60.52 33.56,60.2 33.67,60.23 33.74,60.13 33.74,58.07 36.02,55.78 36.04,55.67 35.95,55.61 35.37,55.61 31.77,59.21 29.85,59.21 29.75,59.27 29.78,59.38 31.66,61.27
DGND on L03_SIG1 (solid shape): outline of 95 points within 44.33,57.72 48.6,64.96
DGND on L03_SIG1 (solid shape): 49.03,93.63 49.03,93.62 49.31,93.34 49.69,93.46 49.87,93.46 49.93,93.4 49.96,93.3 49.89,93.23 49.64,92.7 50.21,92.56 50.27,92.57 50.29,92.52 50.29,92.47 52.28,90.47 52.31,90.38 52.24,90.31 51.99,90.02 52.11,89.65 52.11,89.29 52.05,89.2 51.94,89.22 48.92,92.24 48.92,93.62 48.98,93.68
DGND on L03_SIG1 (solid shape): 101.39,27.82 101.45,27.92 101.56,27.9 102.81,26.64 102.81,22.16 102.75,22.06 102.64,22.09 102.08,22.09 102.12,21.53 102.16,21.45 101.98,21.07 102.16,20.69 102.12,20.61 101.98,20.34 102.07,20.06 102.1,19.99 102.07,19.92 102.03,19.87 101.96,19.82 101.87,19.85 101.83,19.89 101.83,27.04 101.39,27.48
DGND on L03_SIG1 (solid shape): 23.11,11.8 23.15,11.72 23.15,10.02 21.99,8.86 21.99,6.88 21.97,6.32 22.53,6.34 22.64,6.37 22.71,6.28 22.71,4.97 23.36,4.31 23.55,4.31 23.59,4.27 23.61,4.21 23.56,4.18 21.47,4.18 21.3,4.35 21.28,4.43 21.32,4.5 21.47,4.8 21.34,5.1 21.34,8.79 22.06,9.51 22.09,9.51 22.46,9.8 22.26,10.24 22.2,10.31 22.23,10.4 22.68,10.85 22.68,11.71 22.73,11.8 22.81,11.81 22.92,11.8 23.02,11.81
DGND on L03_SIG1 (solid shape): 48.88,33.9 48.99,33.93 49.05,33.83 49.05,33.5 46.01,30.46 46.01,29.41 44.93,28.33 44.83,28.3 44.76,28.38 44.11,28.6 44.33,27.95 44.41,27.88 44.38,27.78 44.21,27.61 44.11,27.58 44.04,27.66 43.4,27.88 43.61,27.23 43.69,27.16 43.67,27.06 43.41,26.8 42.35,26.8 37.5,21.95 37.39,21.93 37.33,22.02 37.33,22.35
DGND on L03_SIG1 (solid shape): outline of 120 points within 48.52,81.16 51.79,88.81
DGND on L03_SIG1 (solid shape): 95.56,7.41 95.64,7.44 95.72,7.4 95.93,7.24 96.2,7.26 96.21,7.27 96.27,7.27 96.27,7.18 96.06,6.97 96.04,6.97 95.66,6.58 96.07,6.21 96.17,6.15 96.15,6.04 96.06,5.96 96.04,5.96 95.66,5.5 96.18,5.22 96.19,5.23 96.25,5.23 96.25,5.13 96.06,4.94 96.04,4.94 95.72,4.77 95.69,4.4 95.69,4.32 95.63,4.26 95.57,4.24 95.52,4.2 95.33,4.01 95.28,4.06 95.15,4.2 95.07,4.25 94.97,4.27 94.68,4.27 94.4,3.99 94.4,3.54 94.12,3.54 94,3.66 94,4.44 95.53,5.98 95.53,7.38
DGND on L03_SIG1 (solid shape): 111.12,51.94 111.23,51.96 111.29,51.86 111.91,50.79 113.14,50.97 113.25,50.99 113.31,50.89 113.31,50.13 113.25,50.04 113.14,50.05 111.29,49.24 113.14,48.43 113.25,48.45 113.31,48.35 113.31,45.87 112.74,45.3 111.88,45.3 110.99,44.4 110.88,44.38 110.82,44.48 110.82,51.63
DGND on L03_SIG1 (solid shape): outline of 130 points within 39.05,58.1 45.72,63.03
DGND on L03_SIG1 (solid shape): 30.27,16.07 30.36,16.01 30.34,15.9 28.93,14.49 28.93,12.66 28.9,12.58 28.81,12.56 28.38,12.18 28.81,11.8 28.9,11.78 28.93,11.7 28.93,9.47 28.89,9.39 28.81,9.37 28.6,9.37 28.43,9.25 27.73,9.25 27.71,9.23 27.6,9.21 27.53,9.3 27.53,13.99 27.58,14.08 27.67,14.09 28.15,14.28 28.01,14.77 27.96,14.84 27.99,14.93 28.54,15.48 28.56,15.48 28.87,15.62 28.94,15.95 28.96,16.03 29.04,16.07
DGND on L03_SIG1 (solid shape): 40.97,47.9 40.97,47.22 40.93,47.14 40.84,47.12 40.35,46.81 40.74,46.38 40.84,46.32 40.82,46.2 40.76,46.14 40.73,46.14 40.35,45.8 40.66,45.38 40.74,45.31 40.71,45.21 40.21,44.71 40.1,44.69 40.04,44.79 40.04,45.62 38.83,46.84 38.35,46.84 38.35,48.55 38.2,48.71 38.12,48.76 38.03,48.78 37.91,48.78 37.82,48.76 37.74,48.71 37.58,48.55 37.46,48.68 37.38,48.73 37.28,48.75 37.15,48.75 37.06,48.73 36.98,48.68 36.84,48.54 36.79,48.53 36.76,48.58 36.76,48.63 36.57,48.82 36.55,48.93 36.64,48.99 38.26,48.99 38.42,49.15 38.47,49.23 38.49,49.32 38.52,49.51 38.59,49.54 39.33,49.54
DGND on L03_SIG1 (solid shape): 86.84,105.7 86.84,105.07 87.89,104.01 88.59,104.01 88.66,103.98 88.69,103.9 88.68,103.8 88.71,103.7 88.69,103.61 88.61,103.56 88,103.56 86.76,104.81 86.76,104.83 86.11,105.11 86.39,104.46 86.41,104.46 86.47,104.39 86.49,104.28 86.4,104.22 86,103.84 86.39,103.46 86.41,103.46 86.47,103.39 86.49,103.28 86.4,103.22 86.06,103.04 86.04,102.66 86.04,102.56 85.95,102.51 82.72,102.51 82.34,102.9 82.34,105.51 82.42,105.59 86.09,105.59 86.44,105.46 86.73,105.7 86.74,105.71 86.78,105.75
DGND on L03_SIG1 (solid shape): 83.36,32.3 83.42,32.39 83.53,32.37 84.25,31.65 84.25,22.6 88.49,18.36 88.49,16.79 89.92,15.37 89.94,15.26 89.84,15.19 89.6,15.19 86.04,18.76 83.99,18.76 83.58,19.16 83.58,28.11 82.78,28.92 82.78,29.12 83.08,29.12 83.29,29.33 83.34,29.41 83.36,29.5 83.36,29.8 83.15,30 83.1,30.05 83.29,30.24 83.31,30.26 83.33,30.29 83.38,30.34 83.46,30.33 83.98,30.77 83.31,30.92 83.24,30.88 83.16,30.91 83.1,30.97 83.29,31.16 83.31,31.18 83.33,31.21 83.38,31.25 83.46,31.25 83.98,31.68 83.31,31.83 83.24,31.79 83.16,31.82 83.1,31.88 83.29,32.07 83.34,32.15 83.36,32.25
DGND on L03_SIG1 (solid shape): outline of 179 points within 60.75,3.98 70.05,15.52
DGND on L03_SIG1 (solid shape): 34.44,58.76 36.33,56.88 45.97,56.88 46.05,56.84 46.07,56.75 46.44,56.27 46.81,56.75 46.83,56.84 46.91,56.88 48.29,56.88 49.2,55.97 49.22,55.86 49.13,55.79 45.54,55.79 45.46,55.84 45.45,55.93 45.09,56.43 44.73,55.93 44.71,55.84 44.63,55.79 44.28,55.79 44.2,55.83 44.18,55.92 43.81,56.37 43.44,55.92 43.42,55.83 43.34,55.79 42.71,55.79 42.63,55.84 42.62,55.94 42.29,56.5 41.95,55.94 41.95,55.84 41.86,55.79 36.71,55.79 34.23,58.27 34.23,58.67 34.27,58.74 34.35,58.77
DGND on L03_SIG1 (solid shape): outline of 214 points within 32.37,41.79 37.99,44.24
DGND on L03_SIG1 (solid shape): outline of 233 points within 104.55,16.37 113.74,29.23
DGND on L03_SIG1 (solid shape): outline of 236 points within 104.63,46.85 111.08,54.52
DGND on L03_SIG1 (solid shape): outline of 253 points within 51.58,57.15 58.72,72.54
DGND on L03_SIG1 (solid shape): outline of 277 points within 88.76,87.32 93.94,95.06
DGND on L03_SIG1 (solid shape): 84.14,56.02 84.2,56.12 84.31,56.09 85.82,54.59 85.85,54.5 85.8,54.43 85.61,53.96 86.05,53.72 86.13,53.69 86.17,53.62 86.17,53.56 86.11,53.56 86.1,53.56 85.59,53.23 86.05,52.83 86.13,52.8 86.17,52.73 86.17,52.67 86.11,52.67 86.1,52.67 85.59,52.34 86.05,51.94 86.13,51.92 86.17,51.84 86.17,49.54 86.56,49.14 86.56,47.46 86.25,47.14 86.25,44.52 85.51,43.78 85.4,43.76 85.34,43.85 85.34,49.03 84.9,49.46 84.9,50.95 84.94,51.02 85.02,51.05 85.47,51.42 85.02,51.8 84.94,51.82 84.9,51.9 84.9,51.95 84.96,51.95 84.97,51.95 85.47,52.28 85.02,52.69 84.94,52.71 84.9,52.79 84.9,52.84 84.96,52.84 84.97,52.84 85.47,53.17 85.02,53.58 84.94,53.6 84.9,53.68 84.9,53.73 84.96,53.73 84.97,53.73 85.4,54.3 84.71,54.12 84.64,54.03 84.53,54.05 84.14,54.44
DGND on L03_SIG1 (solid shape): outline of 129 points within 70.05,40.43 79.16,47.35
DGND on L03_SIG1 (solid shape): outline of 302 points within 22.32,55.05 31.43,61.98
DGND on L03_SIG1 (solid shape): outline of 288 points within 48.78,64.81 50.79,81.64
DGND on L03_SIG1 (solid shape): outline of 352 points within 68.69,82.49 71.75,94.72
DGND on L03_SIG1 (solid shape): outline of 349 points within 41.9,8.73 60.47,27.42
DGND on L03_SIG1 (solid shape): outline of 398 points within 62.22,13.81 70.28,25.17
DGND on L03_SIG1 (solid shape): outline of 457 points within 106.47,29.46 113.74,45.46
DGND on L03_SIG1 (solid shape): outline of 151 points within 30.1,34.12 48.43,45.49
DGND on L03_SIG1 (solid shape): outline of 500 points within 64.91,25.6 74.66,39.45
DGND on L03_SIG1 (solid shape): outline of 550 points within 49.44,64.55 57.21,89.9
DGND on L03_SIG1 (solid shape): outline of 541 points within 54.42,34.27 57.92,42.11
DGND on L03_SIG1 (solid shape): outline of 604 points within 46.93,12.68 55.24,26.2
DGND on L03_SIG1 (solid shape): outline of 767 points within 61.53,84.92 77.8,103.8
DGND on L03_SIG1 (solid shape): outline of 791 points within 98.94,2.65 113.74,16.1
DGND on L03_SIG1 (solid shape): outline of 798 points within 64.84,42.72 74.68,57.82
DGND on L03_SIG1 (solid shape): outline of 919 points within 54.16,51.97 72.52,74.02
DGND on L03_SIG1 (solid shape): outline of 966 points within 42.56,44.5 53.81,55.11
DGND on L03_SIG1 (solid shape): outline of 1243 points within 41.27,74.63 75.57,108.19
DGND on L03_SIG1 (solid shape): outline of 1475 points within 49.5,74.65 70.61,95.71
DGND on L03_SIG1 (solid shape): outline of 1840 points within 60.81,74.15 85.11,107.38
DGND on L03_SIG1 (solid shape): outline of 3037 points within 19.75,7.82 47.75,58.31
DGND on L03_SIG1 (solid shape): outline of 5359 points within 10.02,2.35 88.55,76.7
DGND on L03_SIG1 (solid shape): outline of 5654 points within 90.43,26.55 113.74,108.19
DGND on L08_SIG2 (solid shape): 103.34,26.96 102.56,26.18 102.45,26.16 102.39,26.26 102.39,29.07 102.9,29.59 103.34,29.59
DGND on L08_SIG2 (solid shape): 70.33,56.37 70.33,56.23 69.53,56.23 69.1,56.65 67.71,56.65 67.44,56.92 67.42,57.03 67.51,57.09 69.61,57.09
DGND on L08_SIG2 (solid shape): 106.52,45.2 106.58,45.3 106.69,45.27 107.76,44.21 107.76,38.71 107.49,38.44 107.25,38.68 107.25,44.32 106.52,45.05
DGND on L08_SIG2 (solid shape): 35.13,17.94 35.17,17.89 33.82,16.54 31.38,16.54 31.28,16.6 31.3,16.71 31.65,17.06 34.15,17.06 35.07,17.97
DGND on L08_SIG2 (solid shape): 85.06,105.24 84.73,104.91 82.4,104.91 81.85,104.35 81.75,104.33 81.68,104.41 81.66,104.46 81.65,104.5 81.63,104.53 82.84,105.74 85.06,105.74
DGND on L08_SIG2 (solid shape): 62.33,32.61 62.33,31.98 60.72,30.37 60.18,30.37 60.09,30.43 60.11,30.54 62.26,32.69
DGND on L08_SIG2 (solid shape): 23.88,15.72 23.88,14.6 24.46,14.03 24.46,13.18 24.4,13.09 24.29,13.11 23.72,13.68 23.72,15.37 23.74,15.39 23.74,15.57 23.81,15.65 23.85,15.75
DGND on L08_SIG2 (solid shape): 30.17,8.72 30.21,8.69 30.2,8.64 28.92,7.36 28.24,7.36 27.81,7.79 27.79,7.9 27.88,7.96 29.32,7.96 30.08,8.72
DGND on L08_SIG2 (solid shape): 35.24,15.73 35.35,15.75 35.41,15.66 35.41,14.68 34.79,14.06 33.81,14.06 32.14,12.38 32.01,12.38 31.96,12.41 31.97,12.47
DGND on L08_SIG2 (solid shape): 46.49,30.92 46.58,30.86 46.56,30.75 45.86,30.05 43.13,30.05 43.03,30.11 43.06,30.22 43.76,30.92
DGND on L08_SIG2 (solid shape): 47.87,19.07 47.97,19 47.95,18.89 47.45,18.39 43.49,18.39 43.39,18.45 43.42,18.57 43.92,19.07
DGND on L08_SIG2 (solid shape): 48.32,33.09 48.41,33.02 48.39,32.91 48.2,32.72 41.79,32.72 41.7,32.78 41.72,32.89 41.91,33.09
DGND on L08_SIG2 (solid shape): 71.93,46.74 72,46.84 72.11,46.82 74.22,44.7 74.24,44.59 74.15,44.53 73.7,44.53 71.93,46.3
DGND on L08_SIG2 (solid shape): 78.68,30.29 78.71,30.33 78.76,30.32 80.7,28.39 80.7,27.94 80.64,27.85 80.52,27.87 80.25,28.14 80.25,28.64 78.68,30.22
DGND on L08_SIG2 (solid shape): 90.32,103.19 92.7,103.19 92.82,103.31 92.93,103.34 92.99,103.24 92.99,102.97 92.7,102.67 90.58,102.67 89.44,103.81 89.44,103.89 89.43,103.94 89.42,103.97 89.48,104.03
DGND on L08_SIG2 (solid shape): 98.9,11.66 98.9,11.17 98.84,11.07 98.73,11.09 97.05,12.77 97.03,12.88 97.12,12.94 97.62,12.94
DGND on L08_SIG2 (solid shape): 99.77,13.94 99.79,13.83 99.7,13.77 99.33,13.77 98.03,15.07 98.01,15.18 98.1,15.25 98.46,15.25
DGND on L08_SIG2 (solid shape): 104.34,30.01 104.45,30.03 104.51,29.94 104.51,27.69 104.01,27.19 103.9,27.16 103.84,27.26 103.84,29.5
DGND on L08_SIG2 (solid shape): 63.76,31.15 63.87,31.17 63.93,31.08 63.93,31.03 59.99,27.09 59.7,27.09 59.61,27.15 59.63,27.26 60.9,28.53 61.14,28.53
DGND on L08_SIG2 (solid shape): 67.85,47 67.85,45.12 67.78,45.02 67.67,45.04 67.19,45.53 67.19,47.01 66.8,47.4 66.78,47.51 66.87,47.57 67.27,47.57
DGND on L08_SIG2 (solid shape): 90.93,65.43 91.04,65.45 91.1,65.36 91.1,63.92 92.81,62.21 92.81,61.79 92.74,61.69 92.63,61.72 90.56,63.79 90.56,65.06
DGND on L08_SIG2 (solid shape): 92.55,104.52 92.66,104.54 92.72,104.45 92.72,103.92 92.49,103.69 90.52,103.69 90.07,104.14 90.05,104.25 90.14,104.31 92.34,104.31
DGND on L08_SIG2 (solid shape): 94.57,65.67 94.63,65.76 94.74,65.74 95.07,65.41 95.07,58.66 95.01,58.57 94.9,58.59 93.95,59.55 93.95,61.38 94.57,62
DGND on L08_SIG2 (solid shape): 14.69,32.54 14.8,32.56 14.87,32.47 14.87,28.19 14.07,27.39 14.07,23.3 14.04,23.25 13.98,23.26 13.96,23.28 13.96,26.89 13.06,27.78 13.06,31.48 13.59,32 14.16,32
DGND on L08_SIG2 (solid shape): 64.52,12.79 64.63,12.81 64.69,12.71 64.69,10.64 64.23,10.18 64.19,10.18 64.11,10.22 64.09,10.31 64.1,10.35 64.1,10.42 64.23,10.55 64.23,12.5
DGND on L08_SIG2 (solid shape): 66.47,28.71 66.51,28.63 66.51,27.56 65.68,26.74 65.61,26.73 65.56,26.73 65.47,26.74 65.44,26.82 65.44,27.86 66.3,28.73 66.39,28.73
DGND on L08_SIG2 (solid shape): 84.96,92.81 85.07,92.83 85.13,92.74 85.13,92.47 84.58,91.93 82.74,91.93 82.7,91.89 82.59,91.86 82.53,91.96 82.53,92.11 82.87,92.45 84.6,92.45
DGND on L08_SIG2 (solid shape): 85.11,102.38 85.22,102.4 85.28,102.31 85.28,100.42 85.22,100.33 85.11,100.35 85.09,100.36 82.63,100.36 82.4,100.6 82.4,101.78 82.69,102.08 84.81,102.08
DGND on L08_SIG2 (solid shape): 106.94,45.76 107,45.85 107.11,45.83 109.15,43.79 109.15,38.26 108.09,37.21 107.98,37.18 107.92,37.28 107.92,38.16 108.26,38.5 108.26,44.41 106.94,45.73
DGND on L08_SIG2 (solid shape): 42.25,36 42.34,35.95 42.34,35.85 42.31,35.78 42.3,35.71 42.3,35.69 42.25,35.64 42.17,35.72 39.81,35.72 39.05,34.96 34.38,34.96 33.04,33.62 32.98,33.62 32.93,33.67 34.79,35.52 39.4,35.52 39.87,36
DGND on L08_SIG2 (solid shape): 57.03,29.32 57.03,29.3 57.04,29.24 57.05,29.18 57.03,29.09 56.95,29.05 56.78,29.05 56.61,28.88 55.04,28.88 54.95,28.94 54.97,29.05 55.42,29.5 56.85,29.5
DGND on L08_SIG2 (solid shape): 81.63,26.52 81.7,26.61 81.81,26.58 81.84,26.55 81.84,20.13 75.96,14.25 75.52,14.25 75.43,14.31 75.45,14.42 81.63,20.6
DGND on L08_SIG2 (solid shape): 95.55,73.87 95.65,73.85 96.06,73.44 96.06,66.21 96,66.11 95.89,66.14 95.35,66.68 95.35,73.5 95.44,73.63 95.48,73.78
DGND on L08_SIG2 (solid shape): 68.34,68.86 68.38,68.77 68.38,65.41 69.75,64.05 69.75,57.91 67.77,57.91 67.6,58.07 67.6,68.06 67.81,68.26 67.81,68.75 67.85,68.83 67.94,68.84 68.09,68.82 68.24,68.86
DGND on L08_SIG2 (solid shape): 37.77,15.3 37.82,15.38 37.92,15.39 38.02,15.36 38.14,15.36 38.22,15.34 38.25,15.26 38.25,13.94 33.54,9.22 33.13,9.22 33.04,9.29 33.06,9.4 37.77,14.11
DGND on L08_SIG2 (solid shape): 54.95,32.97 55.03,32.94 55.05,32.86 55.05,32.79 55.07,32.73 55.05,32.64 54.97,32.6 54.12,32.6 53.49,31.96 49.58,31.96 49.49,32.03 49.51,32.14 50.04,32.67 53,32.67 53.31,32.97
DGND on L08_SIG2 (solid shape): 76.15,38.37 76.21,38.46 76.32,38.44 76.64,38.12 76.64,35.46 77.37,34.73 77.4,34.64 77.35,34.56 77.25,34.49 77.18,34.39 77.1,34.34 77.02,34.37 76.15,35.23
DGND on L08_SIG2 (solid shape): 84.95,104.43 85.01,104.44 85.04,104.39 85.04,104.15 84.59,103.7 82.35,103.7 81.85,103.21 81.74,103.19 81.68,103.29 81.68,103.36 81.67,103.43 81.68,103.51 81.75,103.56 82.61,104.41 84.93,104.41
DGND on L08_SIG2 (solid shape): 90.02,85.91 90.08,86 90.19,85.98 90.49,85.68 92.6,85.68 92.81,85.89 92.92,85.91 92.99,85.81 92.99,85.51 92.17,84.69 90.59,84.69 90.19,84.29 90.08,84.27 90.02,84.36
DGND on L08_SIG2 (solid shape): 40.38,44.7 41.99,44.7 42.19,44.89 42.3,44.91 42.36,44.82 42.36,42.6 41.97,42.2 39.93,42.2 39.53,42.61 39.53,44.62 39.65,44.83 39.62,45.08 39.62,45.18 39.71,45.23 39.85,45.23
DGND on L08_SIG2 (solid shape): 33.32,11.14 33.41,11.08 33.39,10.96 32.51,10.08 29.44,10.08 28.74,9.38 28.72,9.39 28.55,9.35 28.41,9.23 28.33,9.19 28.25,9.22 26.5,10.96 26.48,11.08 26.58,11.14
DGND on L08_SIG2 (solid shape): 53.5,28.38 53.58,28.34 53.6,28.26 53.6,28.1 53.66,27.96 53.67,27.85 53.58,27.79 51.56,27.79 49.62,25.85 49.56,25.85 49.46,25.91 49.48,26.02 51.6,28.14 51.6,28.23 51.76,28.38
DGND on L08_SIG2 (solid shape): 78.7,64.86 78.79,64.79 78.76,64.68 78.63,64.42 78.72,64.15 78.01,63.44 74.82,63.44 74.63,63.25 74.45,63.44 73.58,63.44 73.21,63.07 73.21,62.74 72.62,62.74 72.58,62.71 72.53,62.77 72.54,62.8 72.55,62.85 72.55,62.92 74.49,64.86
DGND on L08_SIG2 (solid shape): 77.7,60.64 77.8,60.58 77.77,60.47 77.33,60.03 75.12,60.03 74.74,59.64 74.39,59.64 74.31,59.68 74.3,59.78 74.32,59.87 74.31,59.97 74.33,60.06 74.42,60.1 74.46,60.09 74.71,60.09 74.97,60.35 74.97,60.64
DGND on L08_SIG2 (solid shape): 66.02,84.45 66.13,84.47 66.19,84.38 66.19,82.37 66.78,81.78 66.78,81.24 66.74,81.16 66.65,81.14 66.38,81.12 66.19,80.92 66.12,80.86 66.02,80.89 65.98,80.94 65.98,84.41
DGND on L08_SIG2 (solid shape): 68.82,22.6 68.82,20.09 68.76,20 68.65,20.01 67.94,20.27 67.24,19.99 67.13,19.97 67.07,20.06 67.07,22.13 68.13,23.19 68.13,23.2 68.2,23.23
DGND on L08_SIG2 (solid shape): 49.83,55.35 49.93,55.29 49.9,55.18 48.78,54.06 48.35,54.06 47.97,53.68 47.97,53.27 47.87,53.12 47.84,52.95 47.84,52.92 47.79,52.87 47.71,52.95 47.71,52.97 47.65,53.19 47.47,53.33 47.41,53.4 47.44,53.5 49.29,55.35
DGND on L08_SIG2 (solid shape): 105.94,44.68 106,44.78 106.12,44.75 106.75,44.12 106.75,38.48 107.11,38.12 107.11,36.55 107.05,36.46 106.94,36.47 106.76,36.56 106.56,36.54 106.46,36.55 106.42,36.63 106.42,37.01 106.23,37.2 106.23,43.77 105.94,44.06
DGND on L08_SIG2 (solid shape): 98.11,8.78 98.11,7.92 98.04,7.82 97.93,7.85 97.69,7.98 97.43,7.93 97.33,7.93 97.28,8.02 97.28,8.79 91.43,14.64 91.41,14.75 91.5,14.81 92.07,14.81
DGND on L08_SIG2 (solid shape): 60.01,29.87 60.11,29.81 60.08,29.69 59.44,29.05 57.88,29.05 57.79,29.09 57.78,29.18 57.72,29.52 57.41,29.67 57.39,29.67 57.36,29.69 57.34,29.81 57.44,29.87
DGND on L08_SIG2 (solid shape): 54.34,100.73 54.36,100.62 54.27,100.56 45.48,100.56 44.9,99.98 44.81,99.98 44.73,100 44.69,100.08 44.69,100.39 44.73,100.47 44.81,100.49 45.12,100.58 45.25,100.88 45.25,100.9 46.04,101.68 53.39,101.68
DGND on L08_SIG2 (solid shape): 78.51,60.5 78.6,60.53 78.67,60.47 78.74,60.38 78.83,60.31 78.88,60.24 78.85,60.15 77.62,58.92 75.1,58.92 74.83,58.64 74.39,58.64 74.31,58.68 74.3,58.78 74.32,58.89 74.3,59.01 74.31,59.1 74.39,59.14 74.95,59.14 75.33,59.53 77.53,59.53
DGND on L08_SIG2 (solid shape): 64.6,77.87 64.71,77.9 64.77,77.8 64.77,66.17 64.71,66.07 64.6,66.1 63.84,66.45 63.07,66.15 62.96,66.13 62.89,66.23 62.89,66.33 61.68,67.54 61.68,74.96
DGND on L08_SIG2 (solid shape): 77.61,62.94 77.7,62.88 77.68,62.76 77.68,62.51 77.7,62.41 77.75,62.33 77.87,62.22 77.75,62.11 77.7,62.03 77.68,61.93 77.68,61.78 77.7,61.68 77.75,61.6 77.86,61.5 77.94,61.44 78.04,61.42 78.14,61.36 78.11,61.25 78.01,61.14 75.05,61.14 75,61.17 75.01,61.23 75.06,61.28 75.06,62.94
DGND on L08_SIG2 (solid shape): 38.98,49.49 39.04,49.59 39.16,49.56 39.2,49.52 39.28,49.47 39.37,49.45 39.56,49.42 39.59,49.35 39.59,49.18 41.54,47.24 41.57,47.15 41.52,47.08 41.39,46.94 41.35,46.75 41.35,46.73 41.2,46.58 41.09,46.58 41.09,46.64 41.09,46.65 41.03,46.99 40.72,47.14 40.7,47.14 38.98,48.86
DGND on L08_SIG2 (solid shape): 80.72,26.25 80.83,26.27 80.89,26.17 80.89,20.91 79.01,19.03 78.9,19.01 78.84,19.11 78.84,20.17 79.28,20.62 79.28,20.98 79.32,21.06 79.41,21.08 79.88,21.45 79.41,21.82 79.32,21.84 79.28,21.92 79.28,24.81
DGND on L08_SIG2 (solid shape): 78.37,24.65 78.48,24.67 78.54,24.57 78.54,21.92 78.5,21.83 78.41,21.82 77.92,21.45 78.41,21.09 78.5,21.07 78.54,20.99 78.54,20.96 78.13,20.54 78.13,18.93 77.73,18.53 77.62,18.51 77.55,18.6 77.55,23.83
DGND on L08_SIG2 (solid shape): 29.73,64.49 29.82,64.42 29.8,64.31 28.86,63.37 27.82,63.37 27.65,63.2 27.56,63.18 27.49,63.23 26.87,63.35 26.99,62.73 27.05,62.66 27.02,62.57 26.8,62.35 25.31,62.35 25.22,62.41 25.24,62.52 27.2,64.49
DGND on L08_SIG2 (solid shape): 25.7,10.82 25.76,10.91 25.87,10.89 28.13,8.63 28.15,8.52 28.06,8.46 27.77,8.46 27.05,9.19 27.05,9.21 26.4,9.48 26.67,8.83 26.69,8.83 27.07,8.46 27.09,8.35 27,8.28 26.52,8.28 25.7,9.1
DGND on L08_SIG2 (solid shape): 35.6,14.17 35.71,14.19 35.78,14.1 35.78,13.87 34.3,12.39 34.22,12.36 34.15,12.4 33.57,12.45 33.61,11.87 33.66,11.8 33.63,11.72 33.55,11.64 28.47,11.64 28.37,11.7 28.39,11.81 28.49,11.91 28.53,11.88 28.77,11.8 29,11.89 29.04,11.92 29.07,11.88 32.34,11.88 34.02,13.56 35,13.56
DGND on L08_SIG2 (solid shape): 82.25,19.83 82.26,19.84 82.28,19.85 82.31,19.86 82.34,19.86 82.37,19.84 82.39,19.83 82.41,19.8 82.42,19.77 82.42,19.73 87.63,14.52 90.84,14.52 91.3,14.06 91.31,14.05 91.33,14.02 91.33,13.99 91.33,13.96 91.32,13.93 91.3,13.91 91.28,13.89 91.25,13.88 91.23,13.88 76.55,13.88 76.53,13.88 76.5,13.89 76.48,13.91 76.46,13.93 76.45,13.96 76.44,13.99 76.45,14.02 76.46,14.05 76.47,14.06 77.66,15.24 82.73,15.24 82.74,15.19 82.75,15.13 82.77,15.08 82.8,15.03 82.83,14.99 82.87,14.95 82.92,14.92 82.97,14.89 83.02,14.87 83.07,14.86 83.13,14.86 83.19,14.87 83.24,14.88 83.29,14.9 83.34,14.93 83.38,14.97 83.42,15.01 83.45,15.05 83.47,15.1 83.49,15.16 83.5,15.21 83.5,15.27 83.49,15.32 83.47,15.38 83.45,15.43 83.42,15.47 83.38,15.52 83.34,15.55 83.29,15.58 83.24,15.6 83.19,15.62 83.13,15.62 83.07,15.62 83.02,15.61 82.97,15.59 82.92,15.57 82.87,15.53 82.83,15.5 82.8,15.45 82.77,15.4 82.75,15.35 82.74,15.3 82.73,15.24 77.66,15.24
DGND on L08_SIG2 (solid shape): 37.28,31.12 37.38,31.06 37.36,30.95 29.08,22.67 29.08,17.03 28.95,16.69 29.17,16.4 29.23,16.33 29.2,16.24 29.03,16.07 28.95,16.04 28.88,16.09 28.74,16.2 28.56,16.24 28.54,16.24 28.38,16.41 28.38,23.29 32.04,26.95 32.12,26.98 32.2,26.94 32.63,26.8 32.89,27.17 32.89,27.19 36.81,31.12
DGND on L08_SIG2 (solid shape): 71.42,24.08 71.48,24.17 71.59,24.15 72.29,23.86 73.01,24.11 73.12,24.13 73.18,24.03 73.18,23.89 72,22.7 72,20.01 71.93,19.91 71.82,19.94 71.01,20.27 70.23,19.88 70.12,19.85 70.05,19.94 70.05,22.39 71.42,23.76
DGND on L08_SIG2 (solid shape): 63.08,24.05 63.13,24.04 63.16,24.01 63.12,23.9 63.12,23.79 62.98,23.66 62.98,22.53 62.97,22.51 62.88,22.48 62.81,22.53 62.21,22.6 62.28,22 62.33,21.93 62.3,21.85 59.68,19.22 59.57,19.2 59.5,19.29 59.33,19.62 58.96,19.65 58.87,19.65 58.82,19.74 58.82,20.64 59.95,21.77 60.57,21.77 62.84,24.05
DGND on L08_SIG2 (solid shape): 55.06,99.61 55.08,99.5 54.99,99.43 46.38,99.43 46.37,99.42 46.29,99.39 46.22,99.44 45.64,99.48 45.69,98.9 45.73,98.83 45.7,98.75 45.53,98.58 45.16,98.58 45,98.69 44.81,98.71 44.73,98.73 44.69,98.81 44.69,99.12 44.73,99.2 44.81,99.22 45.12,99.31 45.25,99.61 45.25,99.63 45.68,100.06 54.61,100.06
